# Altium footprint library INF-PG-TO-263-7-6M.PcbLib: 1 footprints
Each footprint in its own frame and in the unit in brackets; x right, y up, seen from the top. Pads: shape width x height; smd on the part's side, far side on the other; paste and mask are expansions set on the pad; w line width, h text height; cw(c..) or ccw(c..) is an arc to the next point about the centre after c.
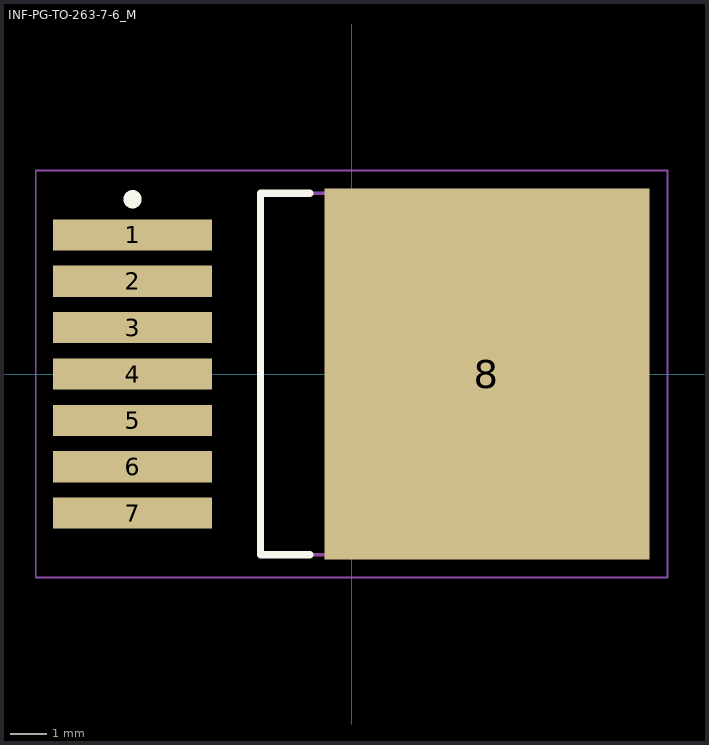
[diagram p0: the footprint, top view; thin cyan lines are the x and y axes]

## INF-PG-TO-263-7-6_M [mm] "DPAK, 7-Leads, Body 9.9x9.2mm, Pitch 1.27mm, IPC Low Density"
height 4.4
pads (8):
  rect 4.35x0.85 smd: 1(-6,3.81) 2(-6,2.54) 3(-6,1.27) 4(-6,0) 5(-6,-1.27) 6(-6,-2.54) 7(-6,-3.81)
  rect 8.9x10.15 smd: 8(3.7,0)
Top Overlay:
  circle w0.25: c-6,4.785 r0.125
  lines w0.2: -1.15,-4.95 -2.5,-4.95 -2.5,4.95 -1.15,4.95
Mechanical 13:
  lines w0.1: -2.5,-4.95 -2.5,4.95 6.9,4.95 6.9,-4.95 -2.5,-4.95
Mechanical 15:
  lines w0.05: -8.65,-5.575 -8.65,5.575 8.65,5.575 8.65,-5.575 -8.65,-5.575
  lines w0.1: -0.5,0 0.5,0 ; 0,-0.5 0,0.5
3D body: height 4.4, standoff 0.1, extent -2.5,-4.95 6.9,4.95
